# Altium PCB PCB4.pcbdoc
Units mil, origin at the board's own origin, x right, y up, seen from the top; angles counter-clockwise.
Board outline 2480 x 895 mil, 2 copper layers (Top Layer, Bottom Layer), stack 62.2 mil thick; 30 components, 28 nets, 153 pads, 27 vias.
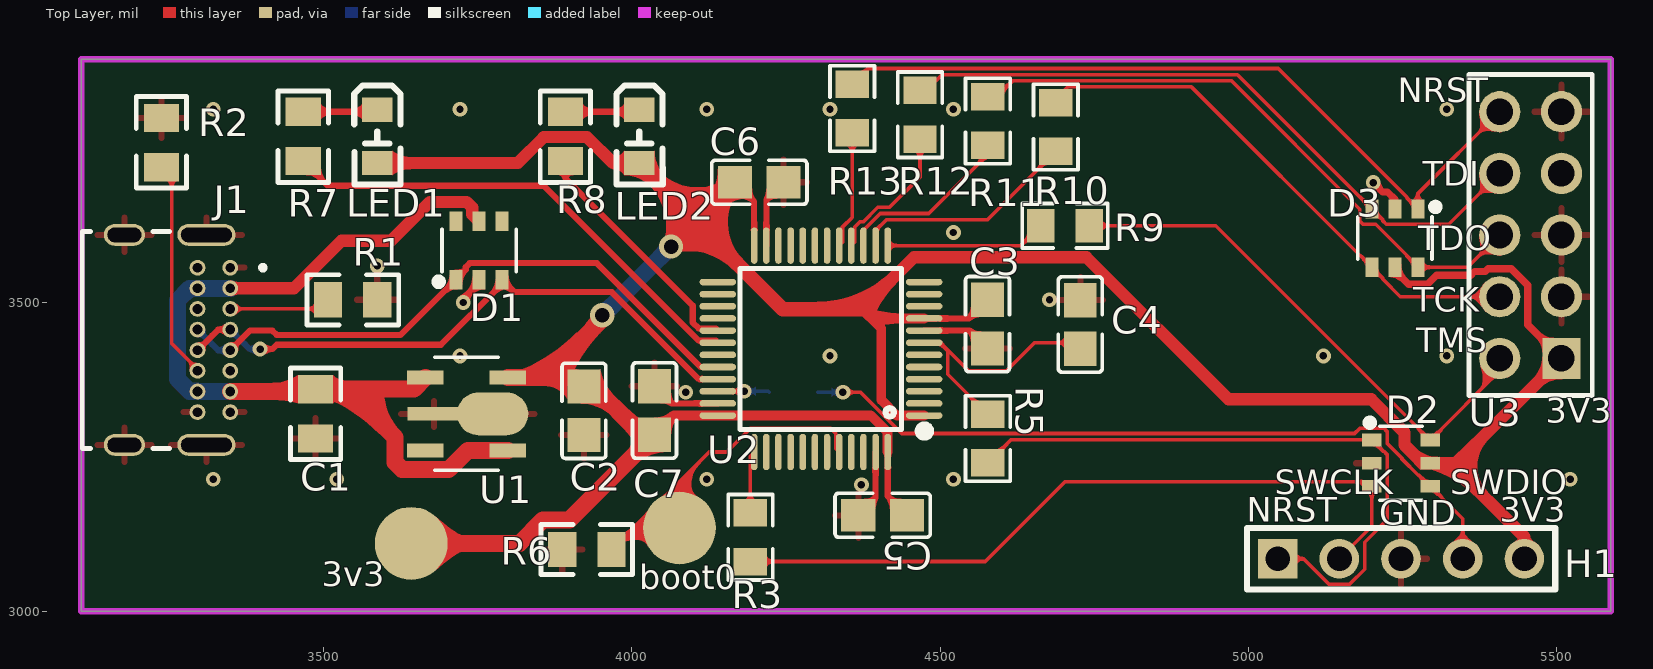
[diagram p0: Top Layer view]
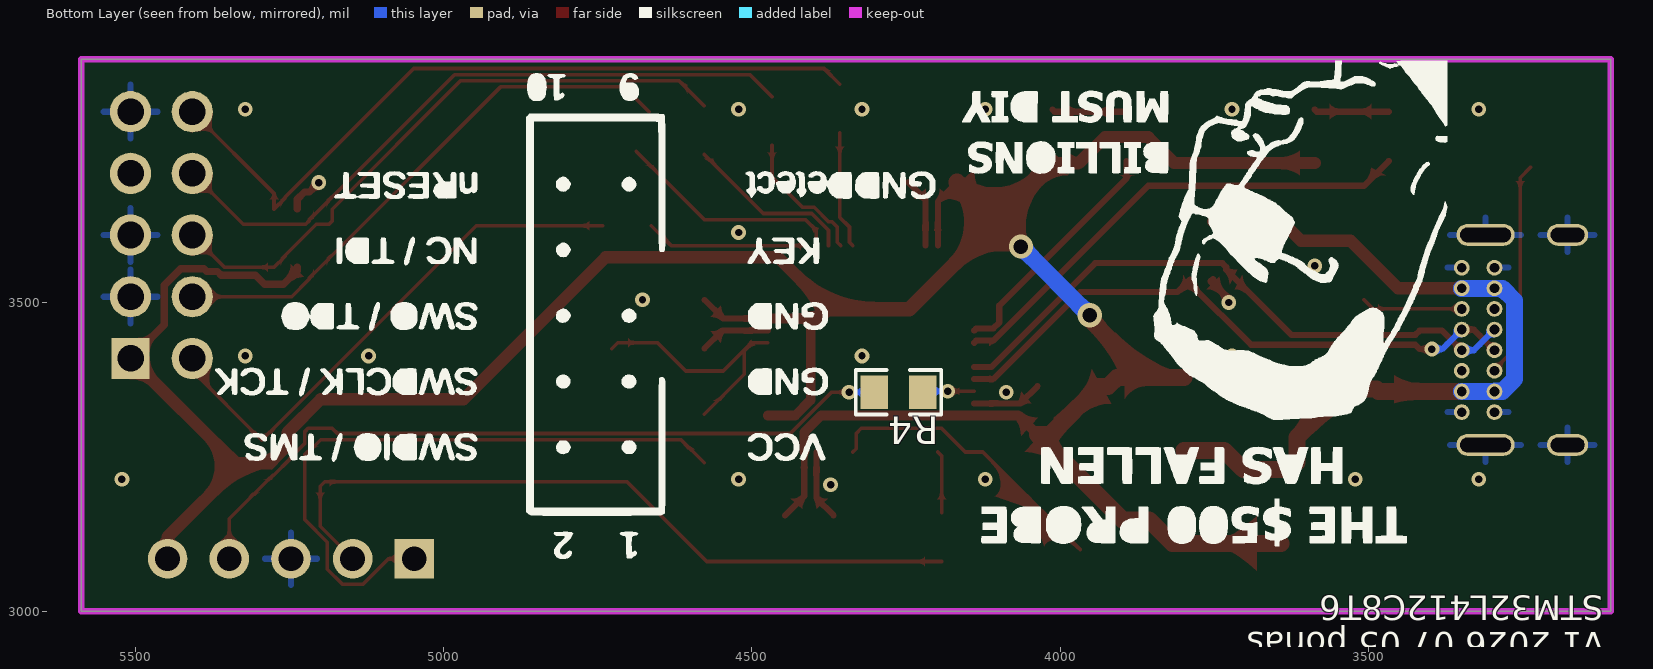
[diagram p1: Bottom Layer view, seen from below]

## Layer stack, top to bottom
Top Solder Mask Layer: solder mask 0.4, Dk 3.3
Top Layer: signal copper 1.4
Dielectric1: surface 59.4, FR4, Dk 4.5
Bottom Layer: signal copper 1.4
Bottom Solder Mask Layer: solder mask 0.4, Dk 3.3

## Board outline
3107.2,3895 3107.2,3000 5587.2,3000 5587.2,3895

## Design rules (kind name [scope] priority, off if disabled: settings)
BoardOutlineClearance copperThickness1oz [All] p0: genericclearance=10 ignorepadtopadclearanceinfootprint=FALSE except(0: Arc-SplitContinuation Track-SplitContinuation SMDPad-SplitContinuation THPad-SplitContinuation Via-SplitContinuation Fill-SplitContinuation Poly-SplitContinuation Region-SplitContinuation Text-SplitContinuation)
BoardOutlineClearance copperThickness2oz [All] p0: genericclearance=10 ignorepadtopadclearanceinfootprint=FALSE except(0: Arc-SplitContinuation Track-SplitContinuation SMDPad-SplitContinuation THPad-SplitContinuation Via-SplitContinuation Fill-SplitContinuation Poly-SplitContinuation Region-SplitContinuation Text-SplitContinuation)
BoardOutlineClearance otherClearance [All] p0: genericclearance=10 ignorepadtopadclearanceinfootprint=FALSE except(0: Arc-SplitContinuation Track-SplitContinuation SMDPad-SplitContinuation THPad-SplitContinuation Via-SplitContinuation Fill-SplitContinuation Poly-SplitContinuation Region-SplitContinuation Text-SplitContinuation)
Clearance copperThickness1oz [All] p1: gap=7 ignorepadtopadclearanceinfootprint=FALSE
Clearance copperThickness2oz [All] p1: gap=7 ignorepadtopadclearanceinfootprint=FALSE
Clearance otherClearance [All] p1: gap=7 ignorepadtopadclearanceinfootprint=FALSE
DiffPairsRouting differentialPair [All] p1: maxuncoupledlength=10 minlimit=6 maxlimit=Infinity mostfreqgap=6 toplayer_minwidth=5 toplayer_prefwidth=10 toplayer_maxwidth=100 bottomlayer_minwidth=5 bottomlayer_prefwidth=10 bottomlayer_maxwidth=100
PasteMaskExpansion pasteMaskExpansion [All] p1: expansion=0
PlaneConnect innerPlane [All] p1: planeconnectstyle=Relief reliefexpansion=20 reliefentries=4 reliefconductorwidth=10 reliefairgap=10
PolygonConnect copperRegion [All] p1: connectstyle=Relief reliefentries=4 reliefconductorwidth=10 polygonreliefangle="90 Angle" airgapwidth=10
RoutingVias viaSize [All] p1: viastyle="Through Hole" holewidth=12.0078 minholewidth=11.811 maxholewidth=248.0314 width=12.0078 minwidth=11.811 maxwidth=248.0314
SolderMaskExpansion solderMaskExpansion [IsVia] p1: useseparateexpansions=TRUE expansion=-1000 expansionbottom=-1000
SolderMaskExpansion solderMaskExpansion [All] p2: useseparateexpansions=TRUE expansion=2 expansionbottom=2
Width copperThickness1oz [All] p1: maxlimit=100 minlimit=5 preferedwidth=6
Width copperThickness2oz [All] p1: maxlimit=100 minlimit=8 preferedwidth=10

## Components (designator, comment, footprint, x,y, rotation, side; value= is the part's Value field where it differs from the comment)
C1 "100nF" 0805 3487.2,3320 r270 top locked
C2 "4.7uF" C0805#1 3922.2,3325 r90 top locked
C3 "4.7uF" C0805#2 4576.6,3465.6 r270 top locked
C4 "4.7uF" C0805#1 4727.2,3465 r90 top locked
C5 "4.7uF" C0805#1 4406.6,3155.6 r180 top locked
C6 "4.7uF" C0805#1 4206.6,3695.6 r0 top locked
C7 "4.7uF" C0805#3 4036.6,3325.6 r90 top locked
D1 "AOZ8105CI" TSOT-23-6_L2.9-W1.6-P0.95-LS2.8-BR#1 3752.2,3585 r270 top locked
D2 "AOZ8105CI" TSOT-23-6_L2.9-W1.6-P0.95-LS2.8-BR#2 5247.2,3240 r180 top locked
D3 "AOZ8105CI" TSOT-23-6_L2.9-W1.6-P0.95-LS2.8-BR#1 5237.2,3605 r90 top locked
H1 "800-10-005-10-001000" HDR-TH_800-10-005-66-001101 5247.2,3085 r0 top locked
J1 "USB4085-GF-A_REVB" GCT_USB4085-GF-A_REVB 3177.2,3440 r270 top locked
LED1 "TJ-S2012EX2T6ALC2R-A5" LED0805-RD 3587.2,3770 r270 top locked
LED2 "TJ-S2012EX2T6ALC2R-A5" LED0805-RD 4012.2,3770 r270 top locked
R1 "100kΩ" 0805 3547.2,3505 r180 top locked
R2 "100kΩ" 0805 3237.2,3760 r270 top locked
R3 "10kΩ" R0805#1 4192.2,3120 r90 top locked
R4 "10kΩ" R0805#2 4262.2,3355 r180 bottom locked
R5 "10kΩ" R0805#1 4577.2,3280 r90 top locked
R6 "100kΩ" 0805 3927.2,3100 r0 top locked
R7 "100kΩ" 0805 3467.2,3770 r90 top locked
R8 "100kΩ" 0805 3892.2,3770 r90 top locked
R9 "10kΩ" R0805#2 4702.2,3625 r180 top locked
R10 "10kΩ" R0805#1 4687.2,3785 r270 top locked
R11 "10kΩ" R0805#1 4577.2,3795 r270 top locked
R12 "10kΩ" R0805#1 4467.2,3805 r270 top locked
R13 "10kΩ" R0805#1 4357.2,3815 r270 top locked
U1 "AP7361C-33Y5-13" SOT-89-5_L4.5-W2.5-P1.50-LS4.5-BR 3732.2,3320 r180 top locked
U2 "STM32L412C8T6" LQFP-48_L7.0-W7.0-P0.50-LS9.0-BL 4306.6,3425.6 r90 top locked
U3 "2x5P 2.54mm" HDR-TH_10P-P2.54-V-F-R2-C5-S2.54-1 5457.2,3610 r90 top locked

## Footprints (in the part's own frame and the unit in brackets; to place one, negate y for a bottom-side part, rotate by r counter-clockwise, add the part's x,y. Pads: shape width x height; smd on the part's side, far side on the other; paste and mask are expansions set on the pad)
0805 [mil]
  rect 45.7x57.1 smd paste+0 mask+4: 1(-40,0) 2(40,0)
  silkscreen extent -75,-41 74,41
C0805#1 [mil]
  rect 55.5x53.1 smd paste-3937 mask+2: 1(-39.4,0) 2(39.4,0)
  silkscreen extent -77,-36 77,36
C0805#2 [mil]
  rect 55.5x53.1 smd paste-3937 mask+2: 1(-39.3,0) 2(39.4,0)
  silkscreen extent -77,-36 77,36
C0805#3 [mil]
  rect 55.5x53.1 smd paste-3937 mask+2: 1(-39.4,0) 2(39.3,0)
  silkscreen extent -77,-36 77,36
GCT_USB4085-GF-A_REVB [mil]
  round 25.6 hole 15.7: A1(-117.1,171.6) A4(-83.7,171.6) A5(-50.2,171.6) A6(-16.7,171.6) A7(16.7,171.6) A8(50.2,171.6) A9(83.7,171.6) A12(117.1,171.6) B1(117.1,118.5) B4(83.7,118.5) B5(50.2,118.5) B6(16.7,118.5) B7(-16.7,118.5) B8(-50.2,118.5) B9(-83.7,118.5) B12(-117.1,118.5)
  oval 35.4x66.9 hole 23.6 slot 55.1 at 90 deg: S1(-170.3,0) S2(170.3,0)
  oval 35.4x94.5 hole 23.6 slot 82.7 at 90 deg: S3(-170.3,133) S4(170.3,133)
  silkscreen extent -176,-69 176,228
HDR-TH_10P-P2.54-V-F-R2-C5-S2.54-1 [mil]
  rect 66.9x62 hole 43.3: 1(-200,-50)
  round 66.9 hole 43.3: 2(-200,50) 3(-100,-50) 4(-100,50) 5(0,-50) 6(0,50) 7(100,-50) 8(100,50) 9(200,-50) 10(200,50)
  silkscreen extent -260,-100 260,100
HDR-TH_800-10-005-66-001101 [mil]
  rect 64.2x64.2 hole 40.2: 1(-200,0)
  round 64.2 hole 40.2: 2(-100,0) 3(0,0) 4(100,0) 5(200,0)
  silkscreen extent -250,-50 250,50
LED0805-RD [mil]
  rect 39.4x49.2 smd: 1(-43.3,0) 2(43.3,0)
  silkscreen extent -83,-37 78,38
LQFP-48_L7.0-W7.0-P0.50-LS9.0-BL [mil]
  oval 10.6x59.1 smd paste+0 mask+2: 1(-108.3,-167.3) 2(-88.6,-167.3) 3(-68.9,-167.3) 4(-49.3,-167.3) 5(-29.6,-167.3) 6(-9.9,-167.3) 7(9.8,-167.3) 8(29.5,-167.3) 9(49.2,-167.3) 10(68.9,-167.3) 11(88.5,-167.3) 12(108.2,-167.3) 25(108.2,167.3) 26(88.5,167.3) 27(68.9,167.3) 28(49.2,167.3) 29(29.5,167.3) 30(9.8,167.3) 31(-9.9,167.3) 32(-29.6,167.3) 33(-49.3,167.3) 34(-68.9,167.3) 35(-88.6,167.3) 36(-108.3,167.3)
  oval 59.1x10.6 smd paste+0 mask+2: 13(167.3,-108.3) 14(167.3,-88.6) 15(167.3,-68.9) 16(167.3,-49.2) 17(167.3,-29.5) 18(167.3,-9.9) 19(167.3,9.8) 20(167.3,29.5) 21(167.3,49.2) 22(167.3,68.9) 23(167.3,88.6) 24(167.3,108.3) 37(-167.4,108.3) 38(-167.4,88.6) 39(-167.4,68.9) 40(-167.4,49.2) 41(-167.4,29.5) 42(-167.4,9.8) 43(-167.4,-9.9) 44(-167.4,-29.5) 45(-167.4,-49.2) 46(-167.4,-68.9) 47(-167.4,-88.6) 48(-167.4,-108.3)
  silkscreen extent -141,-176 130,132
R0805#1 [mil]
  rect 44.6x54.2 smd paste-3937 mask+2: 1(-39.4,0) 2(39.4,0)
  silkscreen extent -69,-36 69,36
R0805#2 [mil]
  rect 44.6x54.2 smd paste-3937 mask+2: 1(-39.3,0) 2(39.4,0)
  silkscreen extent -69,-36 69,36
SOT-89-5_L4.5-W2.5-P1.50-LS4.5-BR [mil]
  rect 59.1x22.6 smd paste-3937 mask+2: 1(66.9,-59.1) 3(66.9,59.1) 4(-66.8,59.1) 5(-66.8,-59.1)
  oval 115.7x69.3 smd paste-3937 mask+2: 2(-42,0)
  rect 87x21.7 smd paste-3937 mask+2: 2(52.9,0)
  silkscreen extent -51,-92 51,92
TSOT-23-6_L2.9-W1.6-P0.95-LS2.8-BR#1 [mil]
  rect 31.5x20.9 smd: 1(47.2,-37.4) 2(47.2,0) 3(47.2,37.4) 4(-47.2,37.4) 5(-47.2,0) 6(-47.2,-37.4)
  silkscreen extent -35,-71 57,60
TSOT-23-6_L2.9-W1.6-P0.95-LS2.8-BR#2 [mil]
  rect 31.5x20.9 smd: 1(47.3,-37.4) 2(47.3,0) 3(47.3,37.4) 4(-47.2,37.4) 5(-47.2,0) 6(-47.2,-37.4)
  silkscreen extent -35,-72 57,60

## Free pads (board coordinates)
  round 118.1 smd: 1(3642.2,3110) 1(4077.2,3135)

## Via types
v1: diameter 24, hole 12, Top Layer to Bottom Layer, 25 vias
v2: diameter 39.4, hole 23.6, Top Layer to Bottom Layer, 2 vias

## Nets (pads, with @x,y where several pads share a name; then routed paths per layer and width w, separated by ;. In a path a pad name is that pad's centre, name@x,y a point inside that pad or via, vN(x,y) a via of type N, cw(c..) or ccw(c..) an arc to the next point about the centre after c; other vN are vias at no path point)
3V3: C2.2 C3.1 C5.1 C6.1 C7.1 D2.5 D3.5 H1.5 LED1.2 LED2.2 pad.1@3642.2,3110 U1.5 U2.1 U2.9 U2.24 U2.36 U2.48 U3.1 | length 5203.6
  Top Layer w9.8: C6.1 4198.3,3664.4 U2.24 ; U2.48 4414.9,3186.7 C5.1 ; U2.9 4546.5,3474.8 C3.1
  Top Layer w11.8: D3.5 5237.2,3552.1 5259.2,3530.1 5290,3530.1 5304.7,3544.9 5360.3,3544.9 5366.3,3550.9 5383.9,3550.9 5388.4,3555.4 5426,3555.4 5452.5,3528.8 5452.5,3464.6 U3.1
  Top Layer w15.7: C7.1 4067.7,3317.3 U2.36 4387.5,3317.3 4414.4,3290.4 4414.4,3258.7 U2.48 ; 4373.2,3490 4388.5,3474.8 ; U2.1 4429.5,3317.3 4404.4,3342.3 4404.4,3458.8 4388.5,3474.8 ; U2.9 4388.5,3474.8
  Top Layer w19.7: LED1.2 3815.1,3726.7 3857.1,3768.7 3927.3,3768.7 3969.2,3726.7 LED2.2 ; 4373.2,3490 4457.3,3574.1 4736.9,3574.1 4967.3,3343.8 5199,3343.8 5252.7,3290 5252.7,3269.4 5282.1,3240 D2.5 5327.4,3240 ; H1.5 5447.2,3120.3 5327.4,3240 ; U3.1 5337.2,3240 5327.4,3240
  Top Layer w23.6: 4103.1,3631.4 4244.5,3490 4373.2,3490
  Top Layer w27.6: pad.1@3642.2,3110 3817.8,3110 3856.1,3148.3 3898.7,3148.3 C7.1 4016,3286.2 3937.8,3364.4 C2.2 3907.5,3379.1 3857.2,3379.1 ; U1.5 3857.2,3379.1 ; v2(3952.2,3480) 3952.2,3474 3857.2,3379.1 ; LED2.2 4103.1,3635.8 4103.1,3631.4 ; v2(4063.5,3591.3) 4063.5,3591.8 4103.1,3631.4 ; C6.1 4103.1,3631.4
  Bottom Layer w27.6: v2(3952.2,3480) v2(4063.5,3591.3)
$1N1739: R8.1 U2.29 | length 393.4
  Top Layer w10: R8.1 3892.2,3702.2 4098.8,3495.6 4098.8,3468 4108.3,3458.5 4135.9,3458.5 U2.29
$1N2153: R7.1 U2.30 | length 794.1
  Top Layer w10: R7.1 3507.2,3690 3857,3690 4108.2,3438.8 4135.9,3438.8 U2.30
$1N5566: J1.B5 R2.2 | length 354.4
  Top Layer w5.9: R2.2 3254.1,3703.1 3254.1,3434.1 3295.7,3392.5 J1.B5
$1N5567: J1.A5 R1.2 | length 164.5
  Top Layer w5.9: J1.A5 3492.4,3490.2 R1.2
$1N5583: LED1.1 R7.2 | length 121.4
  Top Layer w10: R7.2 3583.9,3810 LED1.1
$1N5584: LED2.1 R8.2 | length 121.4
  Top Layer w10: R8.2 4008.9,3810 LED2.1
$1N5586: D2.6 R9.1 U3.2 | length 876.2
  Top Layer w5.9: R9.1 4946.8,3625 D2.6 5407.2,3390.2 U3.2
$1N5588: D3.4 R10.1 U3.4 | length 899.1
  Top Layer w5.9: R10.1@4666.5,3810 4706.8,3850.2 4907.3,3850.2 D3.4 5217.8,3539.8 5217.8,3538.3 5246.1,3510 U3.4
$1N5596: D3.6 R11.1 U3.6 | length 1005.8
  Top Layer w5.9: R11.1@4577.2,3819.4 4618,3860.2 4972.2,3860.2 5180.4,3652 5180.4,3632.8 5185.6,3627.6 5206.2,3627.6 5256.6,3577.2 5256.6,3575.7 D3.6 5354.9,3557.8 U3.6
$1N5598: D3.3 R12.1 U3.8 | length 1090.2
  Top Layer w5.9: R12.1@4467.2,3834.4 4502.9,3870.1 4981.9,3870.1 D3.3 5217.8,3634.3 5217.8,3632.8 5223,3627.6 5324.7,3627.6 U3.8
$1N5600: D3.1 R13.1 U3.10 | length 1236
  Top Layer w5.9: R13.1 4382.8,3880 5048.3,3880 5256.6,3671.7 5256.6,3670.2 D3.1 5274.6,3677.4 U3.10
$1N5608: D2.4 H1.4 R4.1 | length 1214.8
  Top Layer w5.9: v1(4342.2,3355) 4370.7,3355 4437.6,3288.1 5171.8,3288.1 5180.5,3296.8 5219.4,3296.8 5224.6,3291.6 5224.6,3272.4 5248.8,3248.2 5248.8,3246.7 5275,3220.6 5276.4,3220.6 D2.4 5347.2,3149.8 H1.4
  Bottom Layer w5.9: R4.1 v1(4342.2,3355)
$1N5610: D2.3 H1.2 R3.1 | length 1203.8
  Top Layer w5.9: R3.1 4572.8,3080.6 4702.2,3210 5192.5,3210 D2.3 5199.9,3137.8 H1.2
$1N5612: D2.1 H1.1 R5.1 | length 1042.1
  Top Layer w5.9: R5.1 4614.8,3278.2 5199.1,3278.2 D2.1 5217.9,3259.4 5219.4,3259.4 5224.6,3254.2 5224.6,3148.4 5188.2,3112 5188.2,3068 5164.2,3044 5130.2,3044 5089.1,3085 H1.1
+5V: C1.1 D1.5 J1.A4 J1.A9 J1.B4 J1.B9 U1.1 U1.4 | length 1487.9
  Top Layer w19.7: J1.A4 3452.1,3523.7 3529.1,3600.7 3609.5,3600.7 3672.6,3663.8 3731.8,3663.8 3741.1,3654.5 3741.1,3643.3 D1.5
  Top Layer w27.6: J1.A9 3483.5,3356.3 C1.1 3537.5,3360 ; U1.1 3646.3,3360 3537.5,3360 ; U1.4 3734.1,3260.9 3703,3229.9 3627.6,3229.9 3616,3241.5 3616,3281.5 3537.5,3360
  Bottom Layer w27.6: J1.A9 J1.B4 ; J1.A4 J1.B9 3283.1,3523.7 3263.1,3503.7 3263.1,3376.3 3282.2,3357.2 ; 3282.2,3357.2 3294.8,3357.2 J1.B4 ; 3282.2,3357.2 3283.1,3356.3 J1.B4
BOOT0: pad.1@4077.2,3135 R6.2 U2.44 | length 480.8
  Top Layer w5.9: R6.2 4125.4,3258.2 4154,3258.2 4192.4,3296.7 4322.4,3296.7 4330.7,3288.3 4330.7,3263.7 U2.44
D+: D1.3 J1.A6 J1.B6 U2.33 | length 988.2
  Top Layer w10: J1.B6 3305.4,3433 3305.5,3433 3319.4,3446.9 3319.4,3447 3329.1,3456.7 J1.A6 ; v1(3397.2,3425) 3417.2,3425 3424.2,3432 3690.4,3432 3789.6,3531.1 D1.3 3809.9,3517.5 3967.7,3517.5 4108.8,3376.3 U2.33
  Bottom Layer w10: J1.A6 3358.5,3447 3358.7,3447 3372.6,3433.1 3372.6,3433 3380.6,3425 v1(3397.2,3425)
D-: D1.1 J1.A7 J1.B7 U2.32 | length 994.2
  Top Layer w10: J1.A7 3358.5,3433 3358.7,3433 3372.6,3446.9 3372.6,3447 3380.6,3455 3417.2,3455 3424.2,3448 3625,3448 D1.1 3730.7,3553.7 3730.7,3558.1 3737.1,3564.5 3943.3,3564.5 4111.7,3396 U2.32
  Bottom Layer w10: J1.B7 3305.4,3447 3305.5,3447 3319.4,3433.1 3319.4,3433 3329.1,3423.3 J1.A7
GND: C1.2 C2.1 C3.2 C4.2 C5.2 C6.2 C7.2 D1.2 D2.2 D3.2 H1.3 J1.A1 J1.A12 J1.B1 J1.B12 J1.S1 J1.S2 J1.S3 J1.S4 R1.1 R2.1 R6.1 U1.2 U2.8 U2.23 U2.35 U2.47 U3.3 U3.5 U3.9 | length 569.6
  Top Layer w9.8: C7.2 4064.6,3337 U2.35 ; U2.23 4218,3667.6 C6.2 ; C5.2 4395.2,3183.5 U2.47 ; U2.8 4547.7,3455.1 C3.2
  Top Layer w11.8: v1(3726.5,3500.6) 3730.2,3504.2 3730.2,3510.1 3755,3534.9 D1.2 ; v1(5202.2,3695) 5217.3,3679.9 5225.4,3679.9 5237.2,3668.1 D3.2
  other v1: 4372.2,3205 3321.3,3214.1 3521.3,3214.1 4121.3,3214.1 4521.3,3214.1 5521.3,3214.1 4087.2,3355 3721.3,3414.1 4321.3,3414.1 5121.3,3414.1 5321.3,3414.1 4677.2,3505 3587.2,3560 4521.3,3614.1 3321.3,3814.1 3721.3,3814.1 4121.3,3814.1 4321.3,3814.1 4521.3,3814.1 5321.3,3814.1
NRST: C4.1 R5.2 U2.7 | length 444
  Top Layer w5.9: U2.7 U2.7@4498.6,3435.4 ; R5.2 4512.4,3384.1 4512.4,3421.6 U2.7@4498.6,3435.4 ; C4.1 4717.4,3435.4 4652.8,3435.4 4606.9,3389.5 4546.3,3389.5 4500.4,3435.4 U2.7@4498.6,3435.4
SWCLK: R3.2 U2.37 | length 101.3
  Top Layer w5.9: R3.2 4192.2,3252.1 U2.37
SWDIO: R4.2 U2.34 | length 84.2
  Top Layer w5.9: U2.34 v1(4182.2,3356.7)
  Bottom Layer w5.9: v1(4182.2,3356.7) 4221.1,3356.7 R4.2
T_NRST: R13.2 U2.17 | length 191.5
  Top Layer w5.9: U2.17 4341.6,3598.3 4341.6,3623 4357.2,3638.6 R13.2
T_TCK: R10.2 U2.14 | length 369.7
  Top Layer w5.9: U2.14 4395.2,3617.5 4412.7,3635 4576.6,3635 R10.2
T_TDI: R12.2 U2.16 | length 223.3
  Top Layer w5.9: U2.16 4361.3,3598.3 4361.3,3623 4369.6,3631.3 4375.3,3631.3 4398.8,3654.9 4417.8,3654.9 4467.2,3704.2 R12.2@4467.2,3755.6
T_TDO: R11.2 U2.15 | length 277.3
  Top Layer w5.9: U2.15 4375.5,3617.6 4402.9,3645 4481.5,3645 R11.2@4577.2,3740.6
T_TMS: R9.2 U2.13 | length 261.2
  Top Layer w5.9: U2.13 4630.7,3592.9 R9.2
pads on no net: D1.4 D1.6 J1.A8 J1.B8 U1.3 U2.2 U2.3 U2.4 U2.5 U2.6 U2.10 U2.11 U2.12 U2.18 U2.19 U2.20 U2.21 U2.22 U2.25 U2.26 U2.27 U2.28 U2.31 U2.38 U2.39 U2.40 U2.41 U2.42 U2.43 U2.45 U2.46 U3.7

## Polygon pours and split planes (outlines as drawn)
GND on Top Layer (solid, remove dead copper, pour order 0): 3107.2,3895 3107.2,3000 5587.2,3000 5587.2,3895
GND on Bottom Layer (solid, remove dead copper, pour order 2): 3107.2,3895 3107.2,3000 5587.2,3000 5587.2,3895

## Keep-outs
Board Outline Layer:
  the board outline again, w10

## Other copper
Top Layer:
  drawing of 113 lines, arcs and shapes, not listed
Bottom Layer:
  region net D+: 3362,3450.6 3355,3443.5 3348,3444 3361.6,3457.5
  region net D-: 3331.4,3418.3 3331.4,3428.3 3333.2,3428.7 3335.6,3429.7 3338.1,3431.2 3340.4,3432.9 3340.4,3413.7 3338.1,3415.4 3335.6,3416.8 3333.2,3417.9
  region net D-: 3308.9,3450.6 3301.8,3443.5 3294.9,3444 3308.4,3457.5
  region net +5V: 3286,3507.1 3269.8,3529.9 3270.4,3530.3 3271.1,3530.5 3273,3530.4 3275.1,3529.9 3277.4,3529.2 3279.6,3528.5 3281.6,3528 3283,3528 3283.5,3528.2 3283.9,3528.6 3294.9,3510.9 3293.9,3510.9 3292.8,3510.6 3290.3,3509.8 3287.9,3508.6
  region net SWDIO: 4191.6,3353.7 4191.6,3359.6 4194.2,3359.9 4196.6,3360.8 4198.7,3362.2 4200.5,3364 4200.5,3349.3 4198.7,3351.1 4196.6,3352.5 4194.2,3353.4 4191.6,3353.7
  region net $1N5608: 4332.7,3358 4332.7,3352 4330.1,3351.8 4327.7,3350.9 4325.6,3349.5 4323.8,3347.6 4323.8,3362.4 4325.6,3360.5 4327.7,3359.1 4330.1,3358.2 4332.7,3358
  region net D+: 3380.8,3420 3380.8,3430 3382.6,3430.3 3384.9,3431.3 3387.2,3432.5 3389.2,3434 3389.2,3416 3387.2,3417.5 3384.9,3418.7 3382.6,3419.7
  region net 3V3: 3961.4,3508.7 3980.9,3489.2 3977.6,3485.8 3974.7,3482.6 3972.6,3480.1 3971.8,3478.8 3950.9,3499.6 3952.2,3500.5 3954.8,3502.5 3958,3505.4
  region net 3V3: 4054.3,3562.6 4034.8,3582.1 4038.1,3585.5 4041,3588.7 4043,3591.2 4043.8,3592.5 4064.7,3571.7 4063.4,3570.9 4060.9,3568.8 4057.7,3565.9
  region net SWDIO: 4198.5,3359.6 4198.5,3353.7 4197.4,3353.2 4195.3,3351.8 4192.8,3349.9 4190.1,3347.6 4190.1,3365.7 4192.8,3363.4 4195.3,3361.5 4197.4,3360.1
  region net $1N5608: 4325.8,3352 4325.8,3358 4327,3358.5 4329,3359.8 4331.6,3361.8 4334.2,3364 4334.2,3346 4331.6,3348.2 4329,3350.2 4327,3351.5

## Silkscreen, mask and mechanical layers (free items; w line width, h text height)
Top Silkscreen Layer:
  text "NRST" at 5242.2,3825.3 h39.4
  text "TDI" at 5282.2,3690.3 h39.4
  text "TDO" at 5274.9,3585.3 h39.4
  text "TCK" at 5267.2,3485.3 h39.4
  text "TMS" at 5272.2,3420.3 h39.4
  text "3V3" at 5482.2,3305.3 h39.4
  text "SWCLK" at 5042.2,3190 h39.4
  text "SWDIO" at 5327.2,3190 h39.4
  text "NRST" at 4997.2,3145 h39.4
  text "3V3" at 5407.2,3145 h39.4
  text "GND" at 5212.2,3140 h39.4
  text "3v3" at 3497.2,3040.3 h39.4
  text "boot0" at 4012.2,3035.3 h39.4
Bottom Silkscreen Layer:
  drawing of 114 lines, arcs and shapes, not listed
  text "v1 2026 07 05 ponas / STM32L412C8T6" at 3119.3,3025.3 h39.4 r180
